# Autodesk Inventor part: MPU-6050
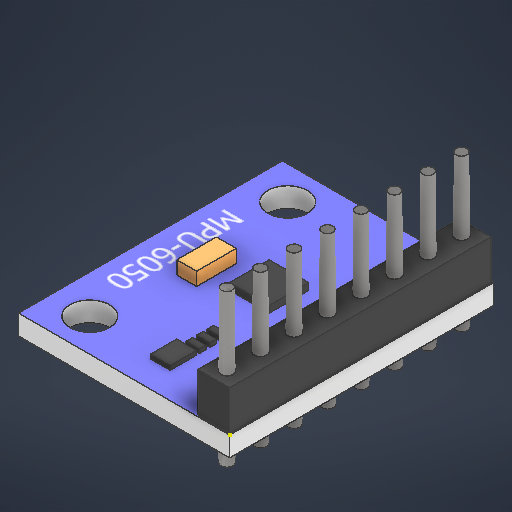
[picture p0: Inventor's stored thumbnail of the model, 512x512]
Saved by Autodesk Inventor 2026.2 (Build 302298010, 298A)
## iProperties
Created: 2026-04
Part Number: MPU-6050
Material: ABS 플라스틱
Document SubType Name: Modeling
Designer: work
Density: 1.06 g/cm^3
Appearance: 매끄러움 - 흰색
Author: work
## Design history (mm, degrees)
sketch "스케치1"
  geometry: L1 (0, 0)-(16, 0); L2 (16, 0)-(16, -20); L3 (16, -20)-(0, -20); L4 (0, -20)-(0, 0); L5 (13.1, -2.5)-(13.1, -17.5); L6 (16, -10)-(0, -10); C1 r 1.5 at (13.1, -2.5); C2 r 1.5 at (13.1, -17.5); 1 further point
  constraints: 12 end point, 3 midpoint, 2 centre point, 2 parallel, 1 horizontal, 1 perpendicular, 1 point on line, 1 vertical
  dimensions: "d0" = 16 distance of L2.end L3.end; "d1" = 20 distance of L1.end L2.end; "d2" = 3 diameter of C1; "d3" = 3 diameter of C2; "d4" = 15 distance of L5.start L5.end; "d5" = 2.9 distance between parallel lines of L2 L5
extrude "돌출1" new body sketch "스케치1" distance "d6" = 1.5; taper "d7" = 0 deg
sketch "스케치2"
  geometry: L1 (-2.5, 0.1)-(-0.1, 0.1); L2 (-0.1, 0.1)-(-0.1, 19.9); L3 (-0.1, 19.9)-(-2.5, 19.9); L4 (-2.5, 19.9)-(-2.5, 0.1); L5 (0, 0)-(0, 20) reference; L6 (0, 10)-(-16, 10); L7 (-16, 20)-(-16, 0) reference; L8 (0, 20)-(-16, 20) reference; L9 (-12.5, 8.5)-(-11, 8.5); L10 (-11, 8.5)-(-11, 11.5); L11 (-11, 11.5)-(-12.5, 11.5); L12 (-12.5, 11.5)-(-12.5, 8.5); L13 (-9.5, 9.5)-(-6.5, 9.5); L14 (-6.5, 9.5)-(-6.5, 12.5); L15 (-6.5, 12.5)-(-9.5, 12.5); L16 (-9.5, 12.5)-(-9.5, 9.5); L17 (-8, 9.5)-(-8, 12.5); L18 (-8, 2)-(-6.5, 2); L19 (-6.5, 2)-(-6.5, 4); L20 (-6.5, 4)-(-8, 4); L21 (-8, 4)-(-8, 2); L22 (-16, 0)-(0, 0) reference; L23 (-7.5, 4.2)-(-6.5, 4.2); L24 (-6.5, 4.2)-(-6.5, 4.7); L25 (-6.5, 4.7)-(-7.5, 4.7); L26 (-7.5, 4.7)-(-7.5, 4.2); L27 (-7.5, 5)-(-6.5, 5); L28 (-6.5, 5)-(-6.5, 5.5); L29 (-7.5, 5.5)-(-7.5, 5); L30 (-6.5, 5.5)-(-7.5, 5.5); L31 (-7.5, 5.8)-(-6.5, 5.8); L32 (-6.5, 5.8)-(-6.5, 6.3); L33 (-7.5, 6.3)-(-7.5, 5.8); L34 (-6.5, 6.3)-(-7.5, 6.3); 7 further points
  constraints: 60 end point, 14 parallel, 11 midpoint, 7 horizontal, 7 perpendicular, 3 point on line, 2 collinear
  dimensions: "d8" = 2.4 distance of L2.end L3.end; "d9" = 0.1 distance between parallel lines of L8 L3; "d10" = 0.1 distance between parallel lines of L5 L2; "d11" = 1.5 distance of L10.end L11.end; "d12" = 3 distance of L11.end L9.start; "d13" = 3.5 distance between parallel lines of L7 L12; "d14" = 3 distance of L15.end L14.end; "d15" = 3 distance of L14.end L13.end; "d16" = 0.5 distance of L17.start point (-8, 10); "d17" = 2 distance of L20.end L18.start; "d18" = 1.5 distance of L19.end L20.end; "d19" = 2 distance from line of L22 point (-7.25, 2); "d20" = 4 distance from line of L4 point (-6.5, 3); "d21" = 0.5 distance of L23.end L24.end; "d22" = 1 distance of L24.end L25.end; "d23" = 0.2 vertical distance of point (-7.25, 4) L23.end; "d24" = 4 distance from line of L4 L24.end; "d25" = 0.5 distance of L27.end L28.end; "d26" = 1 distance of L28.end L29.start; "d27" = 0.3 distance between parallel lines of L25 L27; "d28" = 0.5 distance of L31.end L32.end; "d29" = 1 distance of L32.end L33.start; "d30" = 0.3 distance from line of point (-7, 5.5) L31
extrude "돌출2" join sketch "스케치2" distance "d31" = 0.5; taper "d32" = 0 deg
extrude "돌출3" join sketch "스케치2" distance "d33" = 1; taper "d34" = 0 deg
extrude "돌출4" join sketch "스케치2" distance "d35" = 0.3; taper "d36" = 0 deg
extrude "돌출5" join sketch "스케치2" distance "d37" = 3; taper "d38" = 0 deg
sketch "스케치3" dims "d0" = 16, "d1" = 20, "d2" = 3, "d3" = 3, "d4" = 15, "d5" = 2.9
  geometry: L1 (-13.484, 14.73)-(-13.484, 5.398); L2 (-13.484, 5.398)-(-15.046, 5.398); L3 (-15.046, 5.398)-(-15.046, 14.73); L4 (-15.046, 14.73)-(-13.484, 14.73); 1 further point
  constraints: 2 other
sketch "스케치4"
  geometry: L1 (-0.1, -0.1)-(-0.1, -19.9) reference; L2 (-0.1, -19.9)-(-2.5, -19.9) reference; L3 (-2.5, -19.9)-(-2.5, -0.1) reference; L4 (-2.5, -0.1)-(-0.1, -0.1) reference; L5 (-1.3, -0.1)-(-1.3, -19.9); C1 r 0.5 at (-1.3, -1.1); C2 r 0.5 at (-1.3, -3.64); C3 r 0.5 at (-1.3, -6.18); C4 r 0.5 at (-1.3, -8.72); C5 r 0.5 at (-1.3, -11.26); C6 r 0.5 at (-1.3, -13.8); C7 r 0.5 at (-1.3, -16.34); C8 r 0.5 at (-1.3, -18.88); 1 further point
  constraints: 8 centre point, 2 end point, 2 midpoint, 1 point on line, 1 vertical, 14 other
  dimensions: "d39" = 1 diameter of C1; "d40" = 1 distance of L5.start C1.centre; "d43" = 2.54 distance of C1.centre C2.centre
  node "투영된 루프1"
  node "스케치 - 직사각형 패턴1" dims "d43" = 2.54, "d46" = 10
extrude "돌출6" join sketch "스케치4" distance "d48" = 1.5; taper "d49" = -2 deg
extrude "돌출7" join sketch "스케치4" distance "d50" = 10; taper "d51" = -0.5 deg
node "솔리드1"
